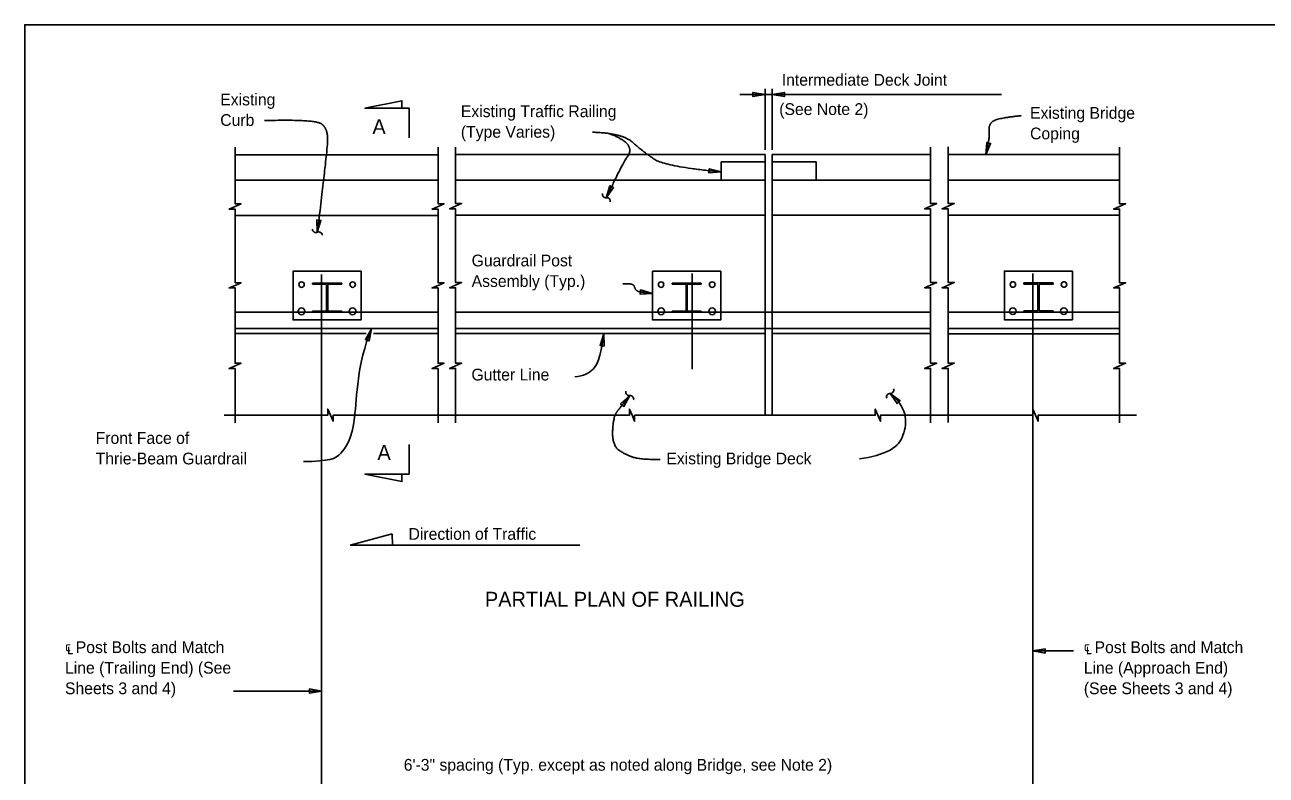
# Model space of a CAD drawing. Extents: x 0 to 41.1, y 0 to 25.9.
# Drawn here: x 0 to 21.27, y 13.09 to 25.95 of the extents above; entities that cross this region are included whole.
import ezdxf

# ---------------------------------------------------------------- set-up
doc = ezdxf.new("R2010")
doc.units = 0
for name, color, linetype in [('Dimension', 7, 'Continuous'), ('ExistSuperStruct', 7, 'Continuous'), ('Miscellaneous1', 7, 'Continuous'), ('SteelMisc', 7, 'Continuous'), ('TextStructures', 7, 'Continuous')]:
    doc.layers.add(name, color=color, linetype=linetype)

msp = doc.modelspace()

# ---------------------------------------------------------------- linework, layer by layer
at = {"layer": 'Dimension'}
for p, q in [((16.732, 24.751), (12.251, 24.751)), ((12.682, 23.804), (12.682, 24.852)), ((12.805, 23.804), (12.805, 24.852)), ((5.827, 24.518), (6.46, 24.645)), ((6.587, 24.518), (5.827, 24.518)), ((6.46, 24.645), (6.46, 24.518)), ((6.587, 24.012), (6.587, 24.518)), ((5.085, 7.662), (5.085, 21.669)), ((11.432, 20.047), (11.432, 21.686)), ((17.272, 7.641), (17.272, 21.686)), ((6.587, 18.753), (6.587, 18.246)), ((6.587, 18.246), (5.827, 18.246)), ((5.827, 18.246), (6.46, 18.12)), ((6.46, 18.12), (6.46, 18.246)), ((5.574, 17.032), (6.295, 17.224)), ((9.384, 17.032), (5.574, 17.032)), ((6.295, 17.224), (6.297, 17.032)), ((6.297, 17.032), (9.51, 17.032)), ((9.51, 17.032), (9.384, 17.032)), ((17.966, 15.217), (17.272, 15.217)), ((3.574, 14.531), (5.085, 14.531))]:
    msp.add_line(p, q, dxfattribs=at)
for points in [[(12.682, 24.751), (12.474, 24.787), (12.474, 24.716)], [(12.805, 24.751), (13.013, 24.716), (13.013, 24.787)], [(6.46, 24.518), (6.46, 24.645), (5.827, 24.518)], [(16.462, 23.72), (16.547, 23.913), (16.479, 23.931)], [(11.928, 23.426), (11.725, 23.481), (11.718, 23.411)], [(9.962, 22.984), (10.083, 23.157), (10.02, 23.187)], [(5.011, 22.393), (5.072, 22.595), (5.002, 22.604)], [(10.752, 21.342), (10.55, 21.403), (10.541, 21.333)], [(5.939, 20.739), (5.836, 20.554), (5.902, 20.531)], [(9.921, 20.652), (9.855, 20.452), (9.924, 20.441)], [(10.363, 19.594), (10.263, 19.408), (10.208, 19.451)], [(14.827, 19.631), (14.945, 19.456), (14.996, 19.504)], [(6.46, 18.246), (6.46, 18.12), (5.827, 18.246)], [(17.272, 15.217), (17.48, 15.182), (17.48, 15.252)], [(5.085, 14.531), (4.877, 14.566), (4.877, 14.495)]]:
    msp.add_lwpolyline(points, close=True, dxfattribs=at)
for points in [[(3.602, 22.322), (3.602, 22.79), (3.499, 22.79), (3.602, 22.835), (3.705, 22.88), (3.602, 22.88), (3.602, 23.85)], [(7.079, 22.322), (7.079, 22.79), (6.976, 22.79), (7.079, 22.835), (7.182, 22.88), (7.079, 22.88), (7.079, 23.85)], [(7.379, 22.324), (7.379, 22.793), (7.276, 22.793), (7.379, 22.838), (7.482, 22.883), (7.379, 22.883), (7.379, 23.852)], [(15.519, 22.324), (15.519, 22.793), (15.416, 22.793), (15.519, 22.838), (15.623, 22.883), (15.519, 22.883), (15.519, 23.852)], [(15.819, 22.326), (15.819, 22.795), (15.716, 22.795), (15.819, 22.84), (15.923, 22.885), (15.819, 22.885), (15.819, 23.854)], [(18.755, 22.322), (18.755, 22.79), (18.652, 22.79), (18.755, 22.835), (18.858, 22.88), (18.755, 22.88), (18.755, 23.85)], [(3.602, 20.574), (3.602, 21.437), (3.499, 21.437), (3.602, 21.482), (3.705, 21.527), (3.602, 21.527), (3.602, 22.322)], [(7.079, 20.574), (7.079, 21.437), (6.976, 21.437), (7.079, 21.482), (7.182, 21.527), (7.079, 21.527), (7.079, 22.322)], [(7.379, 20.576), (7.379, 21.44), (7.276, 21.44), (7.379, 21.485), (7.482, 21.53), (7.379, 21.53), (7.379, 22.324)], [(15.519, 20.576), (15.519, 21.44), (15.416, 21.44), (15.519, 21.485), (15.623, 21.53), (15.519, 21.53), (15.519, 22.324)], [(15.819, 20.578), (15.819, 21.442), (15.716, 21.442), (15.819, 21.487), (15.923, 21.532), (15.819, 21.532), (15.819, 22.326)], [(18.755, 20.574), (18.755, 21.437), (18.652, 21.437), (18.755, 21.482), (18.858, 21.527), (18.755, 21.527), (18.755, 22.322)], [(3.602, 19.127), (3.602, 20.056), (3.499, 20.056), (3.602, 20.101), (3.705, 20.146), (3.602, 20.146), (3.602, 21.018)], [(7.079, 19.127), (7.079, 20.056), (6.976, 20.056), (7.079, 20.101), (7.182, 20.146), (7.079, 20.146), (7.079, 21.018)], [(7.379, 19.129), (7.379, 20.058), (7.276, 20.058), (7.379, 20.103), (7.482, 20.148), (7.379, 20.148), (7.379, 21.021)], [(15.519, 19.129), (15.519, 20.058), (15.416, 20.058), (15.519, 20.103), (15.623, 20.148), (15.519, 20.148), (15.519, 21.021)], [(15.819, 19.131), (15.819, 20.06), (15.716, 20.06), (15.819, 20.105), (15.923, 20.15), (15.819, 20.15), (15.819, 21.023)], [(18.755, 19.127), (18.755, 20.056), (18.652, 20.056), (18.755, 20.101), (18.858, 20.146), (18.755, 20.146), (18.755, 21.018)], [(3.413, 19.257), (5.19, 19.257), (5.19, 19.361), (5.235, 19.257), (5.28, 19.154), (5.28, 19.257), (6.019, 19.257)], [(6.019, 19.257), (10.358, 19.257), (10.358, 19.361), (10.403, 19.257), (10.448, 19.154), (10.448, 19.257), (11.188, 19.257)], [(11.188, 19.257), (14.569, 19.257), (14.569, 19.361), (14.614, 19.257), (14.659, 19.154), (14.659, 19.257), (15.631, 19.257)], [(15.631, 19.257), (17.27, 19.257), (17.27, 19.361), (17.315, 19.257), (17.36, 19.154), (17.36, 19.257), (19.044, 19.257)]]:
    msp.add_lwpolyline(points, dxfattribs=at)
for centre, start, end in [((9.954, 23.043), 166.2264, 277.9536), ((9.971, 22.925), 346.2264, 97.9536), ((4.986, 22.447), 183.5526, 295.2798), ((5.037, 22.339), 3.5526, 115.2798), ((10.356, 19.652), 166.2264, 277.9536), ((10.372, 19.534), 346.2264, 97.9536), ((14.824, 19.571), 87.6771, 199.4043), ((14.829, 19.69), 267.6771, 19.4043)]:
    msp.add_arc(centre, 0.0596, start, end, dxfattribs=at)
for points, degree in [([(4.107, 24.305), (4.991, 24.33), (5.188, 24.16), (5.188, 23.821), (5.012, 22.393)], 2), ([(17.072, 24.389), (16.715, 24.355), (16.508, 24.258), (16.536, 24.015), (16.462, 23.72)], 2), ([(9.725, 24.106), (10.233, 24.093), (10.596, 23.769), (10.972, 23.518), (11.928, 23.426)], 2), ([(10.03, 24.075), (10.279, 23.98), (10.398, 23.782), (10.253, 23.598), (9.962, 22.984)], 2), ([(10.244, 21.509), (10.332, 21.512), (10.439, 21.494), (10.463, 21.384), (10.609, 21.36), (10.752, 21.342)], 2), ([(4.773, 18.463), (5.222, 18.468), (5.417, 18.545), (5.697, 19.02), (5.687, 20.127), (5.939, 20.739)], 3), ([(9.421, 19.916), (9.575, 19.927), (9.761, 20.025), (9.852, 20.207), (9.921, 20.652)], 3), ([(10.885, 18.498), (10.554, 18.498), (10.326, 18.564), (10.06, 18.729), (10.081, 19.23), (10.191, 19.379), (10.364, 19.593)], 2), ([(14.298, 18.511), (14.504, 18.534), (14.893, 18.647), (15.062, 18.892), (15.131, 19.279), (14.952, 19.527), (14.827, 19.631)], 3)]:
    msp.add_open_spline(points, degree=degree, dxfattribs=at)
at = {"layer": 'ExistSuperStruct'}
for p, q in [((3.602, 23.721), (7.079, 23.721)), ((12.682, 23.723), (7.379, 23.723)), ((12.682, 23.723), (12.682, 19.247)), ((12.805, 23.723), (12.805, 19.247)), ((12.805, 23.723), (15.519, 23.723)), ((18.755, 23.723), (15.819, 23.723)), ((11.932, 23.598), (12.682, 23.598)), ((13.555, 23.598), (12.805, 23.598)), ((7.079, 23.284), (3.602, 23.284)), ((7.379, 23.286), (12.682, 23.286)), ((15.519, 23.286), (12.805, 23.286)), ((15.819, 23.286), (18.755, 23.286)), ((7.079, 22.68), (3.602, 22.68)), ((7.379, 22.682), (12.682, 22.682)), ((15.519, 22.682), (12.805, 22.682)), ((15.819, 22.682), (18.755, 22.682)), ((5.85, 20.657), (3.602, 20.657)), ((7.079, 20.657), (5.971, 20.657)), ((12.682, 20.657), (7.379, 20.657)), ((15.519, 20.657), (12.805, 20.657)), ((15.819, 20.652), (18.755, 20.652))]:
    msp.add_line(p, q, dxfattribs=at)
for points in [[(11.932, 23.598), (11.932, 23.286)], [(13.555, 23.598), (13.555, 23.286)]]:
    msp.add_lwpolyline(points, dxfattribs=at)
at = {"layer": 'Miscellaneous1'}
msp.add_lwpolyline([(0, 25.946), (41.051, 25.946), (41.051, 0), (0, 0)], close=True, dxfattribs=at)
at = {"layer": 'SteelMisc'}
for p, q in [((4.929, 21.521), (5.429, 21.521)), ((4.929, 21.521), (4.929, 21.5)), ((4.929, 21.5), (5.158, 21.5)), ((5.168, 21.49), (5.168, 21.042)), ((5.189, 21.49), (5.189, 21.042)), ((5.2, 21.5), (5.429, 21.5)), ((5.429, 21.521), (5.429, 21.5)), ((11.589, 21.521), (11.089, 21.521)), ((11.089, 21.521), (11.089, 21.5)), ((11.318, 21.5), (11.089, 21.5)), ((11.328, 21.49), (11.328, 21.042)), ((11.349, 21.49), (11.349, 21.042)), ((11.589, 21.5), (11.359, 21.5)), ((11.589, 21.521), (11.589, 21.5)), ((17.116, 21.523), (17.616, 21.523)), ((17.116, 21.523), (17.116, 21.502)), ((17.116, 21.502), (17.345, 21.502)), ((17.355, 21.492), (17.355, 21.044)), ((17.376, 21.492), (17.376, 21.044)), ((17.387, 21.502), (17.616, 21.502)), ((17.616, 21.523), (17.616, 21.502)), ((7.079, 21.021), (3.602, 21.021)), ((4.929, 21.042), (5.168, 21.042)), ((4.929, 21.021), (4.929, 21.042)), ((4.929, 21.021), (5.429, 21.021)), ((5.189, 21.042), (5.429, 21.042)), ((5.429, 21.021), (5.429, 21.042)), ((15.519, 21.021), (7.379, 21.021)), ((11.328, 21.042), (11.089, 21.042)), ((11.089, 21.021), (11.089, 21.042)), ((11.589, 21.021), (11.089, 21.021)), ((11.589, 21.042), (11.349, 21.042)), ((11.589, 21.021), (11.589, 21.042)), ((15.819, 21.021), (18.755, 21.021)), ((17.116, 21.044), (17.355, 21.044)), ((17.116, 21.023), (17.116, 21.044)), ((17.116, 21.023), (17.616, 21.023)), ((17.376, 21.044), (17.616, 21.044)), ((17.616, 21.023), (17.616, 21.044)), ((7.079, 20.741), (3.602, 20.741)), ((15.519, 20.741), (7.379, 20.741)), ((15.819, 20.741), (18.755, 20.741))]:
    msp.add_line(p, q, dxfattribs=at)
for points in [[(4.596, 20.891), (5.762, 20.891), (5.762, 21.724), (4.596, 21.724), (4.596, 20.891), (4.596, 20.891)], [(11.922, 20.891), (10.755, 20.891), (10.755, 21.724), (11.922, 21.724), (11.922, 20.891), (11.922, 20.891)], [(16.782, 20.893), (17.949, 20.893), (17.949, 21.726), (16.782, 21.726), (16.782, 20.893), (16.782, 20.893)]]:
    msp.add_lwpolyline(points, dxfattribs=at)
for centre, radius in [((4.741, 21.495), 0.0469), ((5.616, 21.495), 0.0469), ((10.901, 21.495), 0.0469), ((11.776, 21.495), 0.0469), ((16.928, 21.497), 0.0469), ((17.803, 21.497), 0.0469), ((4.741, 21.037), 0.0573), ((5.616, 21.037), 0.0573), ((10.901, 21.037), 0.0573), ((11.776, 21.037), 0.0573), ((16.928, 21.039), 0.0573), ((17.803, 21.039), 0.0573)]:
    msp.add_circle(centre, radius, dxfattribs=at)
for centre, start, end in [((5.158, 21.49), 0, 90), ((5.2, 21.49), 90, 180), ((11.318, 21.49), 0, 90), ((11.359, 21.49), 90, 180), ((17.345, 21.492), 0, 90), ((17.387, 21.492), 90, 180)]:
    msp.add_arc(centre, 0.0104, start, end, dxfattribs=at)
at = {"layer": 'TextStructures'}
msp.add_lwpolyline([(0, 0), (41.051, 0), (41.051, 25.946), (0, 25.946)], close=True, dxfattribs=at)

# ---------------------------------------------------------------- texts
at = {"layer": 'Dimension'}
for s, p in [('Existing ', (3.348, 24.566)), ('Existing Traffic Railing', (7.47, 24.364)), ('Existing Bridge ', (17.222, 24.336)), ('Curb', (3.348, 24.214)), ('(Type Varies)', (7.47, 24.012)), ('Coping ', (17.222, 23.984)), ('Guardrail Post ', (7.655, 21.807)), ('Assembly (Typ.)', (7.655, 21.455)), ('Front Face of ', (1.214, 18.766)), ('Thrie-Beam Guardrail', (1.214, 18.414)), ('℄ Post Bolts and Match ', (0.688, 15.181)), ('℄ Post Bolts and Match ', (18.143, 15.181)), ('Line (Trailing End) (See ', (0.688, 14.829)), ('Line (Approach End)', (18.143, 14.829)), ('Sheets 3 and 4)', (0.688, 14.477)), ('(See Sheets 3 and 4)', (18.143, 14.477))]:
    msp.add_text(s, height=0.2016, dxfattribs=at).set_placement(p)
at = {"layer": 'TextStructures'}
for s, height, p in [('Intermediate Deck Joint', 0.2016, (12.968, 24.903)), ('(See Note 2)', 0.2016, (12.925, 24.401)), ('A', 0.256, (5.955, 24.073)), ('Gutter Line', 0.2016, (7.652, 19.852)), ('A', 0.256, (6.041, 18.491)), ('Existing Bridge Deck', 0.2016, (10.991, 18.415)), ('PARTIAL PLAN OF RAILING', 0.256, (7.882, 15.975)), ('6\'-3" spacing (Typ. except as noted along Bridge, see Note 2)', 0.2016, (6.492, 13.166))]:
    msp.add_text(s, height=height, dxfattribs=at).set_placement(p)
msp.add_text('Direction of Traffic', height=0.2016, rotation=359.9998, dxfattribs=at).set_placement((6.574, 17.122))

doc.saveas('drawing.dxf')
